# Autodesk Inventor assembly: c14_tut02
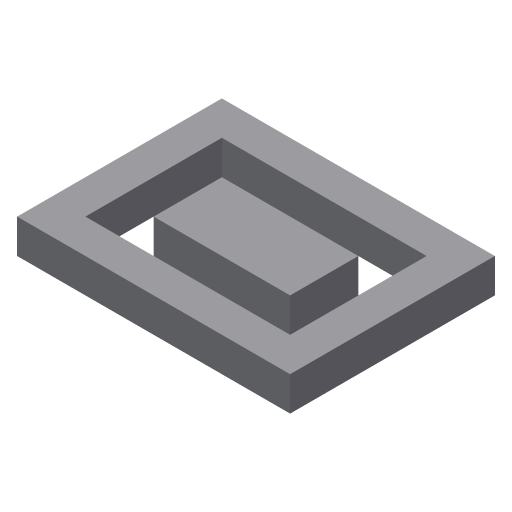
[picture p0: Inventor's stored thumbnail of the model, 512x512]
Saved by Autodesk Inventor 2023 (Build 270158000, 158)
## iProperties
Created: 2010-04
Part Number: c14_tut02
Document SubType Name: Assembly
Designer: CADSoft
Author: CADSoft
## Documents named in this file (3)
- D:\PROJECTS\Project 2022\Autodesk Inventor For Professional 2023\RESOURCES INVENTOR 2023\RESOURCES INVENTOR 2023\Inventor_2023_tut\Inventor_2023_tut\c18_Inv_2023_tut\c18_Inv_tut_2023\c18_tut02_inv\c18_tut02_inv.iam
- D:\PROJECTS\Project 2022\Autodesk Inventor For Professional 2023\RESOURCES INVENTOR 2023\RESOURCES INVENTOR 2023\Inventor_2023_tut\Inventor_2023_tut\c18_Inv_2023_tut\c18_Inv_tut_2023\c18_tut02_inv\Outer Plate.ipt
- D:\PROJECTS\Project 2022\Autodesk Inventor For Professional 2023\RESOURCES INVENTOR 2023\RESOURCES INVENTOR 2023\Inventor_2023_tut\Inventor_2023_tut\c18_Inv_2023_tut\c18_Inv_tut_2023\c18_tut02_inv\Inner Plate.ipt
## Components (2 placed, 2 different names)
1. Outer Plate:1 — Flush:1, Flush:2, Mate:1, Mate:2, Mate:3, Mate:4
2. Inner Plate:1 — Flush:1, Flush:2, Mate:1, Mate:2, Mate:3, Mate:4
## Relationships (6: Mate 4, Flush 2)
- Flush:1: Outer Plate:1 ↔ Inner Plate:1
- Flush:2: Outer Plate:1 ↔ Inner Plate:1
- Mate:1: Outer Plate:1 ↔ Inner Plate:1
- Mate:2: Outer Plate:1 ↔ Inner Plate:1
- Mate:3: Outer Plate:1 ↔ Inner Plate:1
- Mate:4: Outer Plate:1 ↔ Inner Plate:1
